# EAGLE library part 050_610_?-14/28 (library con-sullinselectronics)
.050 DIP EDGE CARD CONNECTOR .050 [1.27mm] CONTACT CENTERS .610" INSULATEOR HEIGHT Source: .050 DIP EDGE CARD.pdf
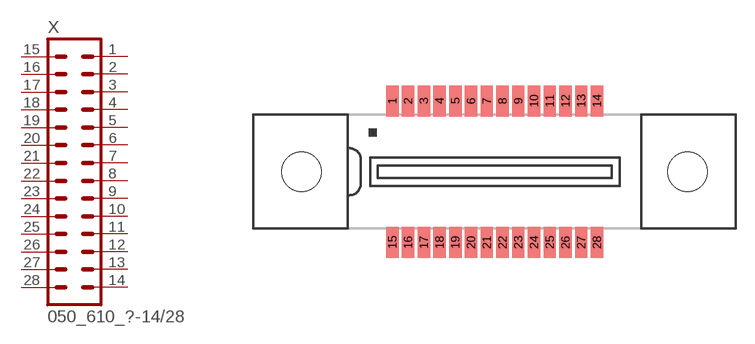
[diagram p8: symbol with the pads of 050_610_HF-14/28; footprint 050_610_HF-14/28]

Designator prefix X

## 050_610_-14/28 (OC_FARNELL: unknown; OC_NEWARK: unknown)  [050_610_HF-14/28]
1  1  pas
2  2  pas
3  3  pas
4  4  pas
5  5  pas
6  6  pas
7  7  pas
8  8  pas
9  9  pas
10  10  pas
11  11  pas
12  12  pas
13  13  pas
14  14  pas
15  15  pas
16  16  pas
17  17  pas
18  18  pas
19  19  pas
20  20  pas
21  21  pas
22  22  pas
23  23  pas
24  24  pas
25  25  pas
26  26  pas
27  27  pas
28  28  pas

## Footprint 050_610_HF-14/28 (pad centres in mm)
.050 DIP EDGE CARD CONNECTOR SURFACE MOUNT .050 [1.27mm] CONTACT CENTERS .610" INSULATEOR HEIGHT Source: .050 DIP EDGE CARD.pdf
smd 1 x 2.5: 1 -8.255,5.715; 2 -6.985,5.715; 3 -5.715,5.715; 4 -4.445,5.715; 5 -3.175,5.715; 6 -1.905,5.715; 7 -0.635,5.715; 8 0.635,5.715; 9 1.905,5.715; 10 3.175,5.715; 11 4.445,5.715; 12 5.715,5.715; 13 6.985,5.715; 14 8.255,5.715; 15 -8.255,-5.715; 16 -6.985,-5.715; 17 -5.715,-5.715; 18 -4.445,-5.715; 19 -3.175,-5.715; 20 -1.905,-5.715; 21 -0.635,-5.715; 22 0.635,-5.715; 23 1.905,-5.715; 24 3.175,-5.715; 25 4.445,-5.715; 26 5.715,-5.715; 27 6.985,-5.715; 28 8.255,-5.715
hole 3.18 at -15.57,0
hole 3.18 at 15.57,0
